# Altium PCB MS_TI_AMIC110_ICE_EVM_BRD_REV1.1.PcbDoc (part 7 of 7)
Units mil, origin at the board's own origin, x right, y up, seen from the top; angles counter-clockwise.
Board outline 3464.57 x 2204.72 mil, 8 copper layers (TopLayer - S1 (.GTL), MidLayer1 - S2 (.G1), MidLayer2 - S3 (.G2), MidLayer3 - S4 (.G3), MidLayer4 - S5 (.G4), MidLayer5 - S6 (.G5), MidLayer6 - S7 (.G6), BottomLayer - S8 (.GBL)), stack 58.937 mil thick; 504 components, 369 nets, 1811 pads, 874 vias.
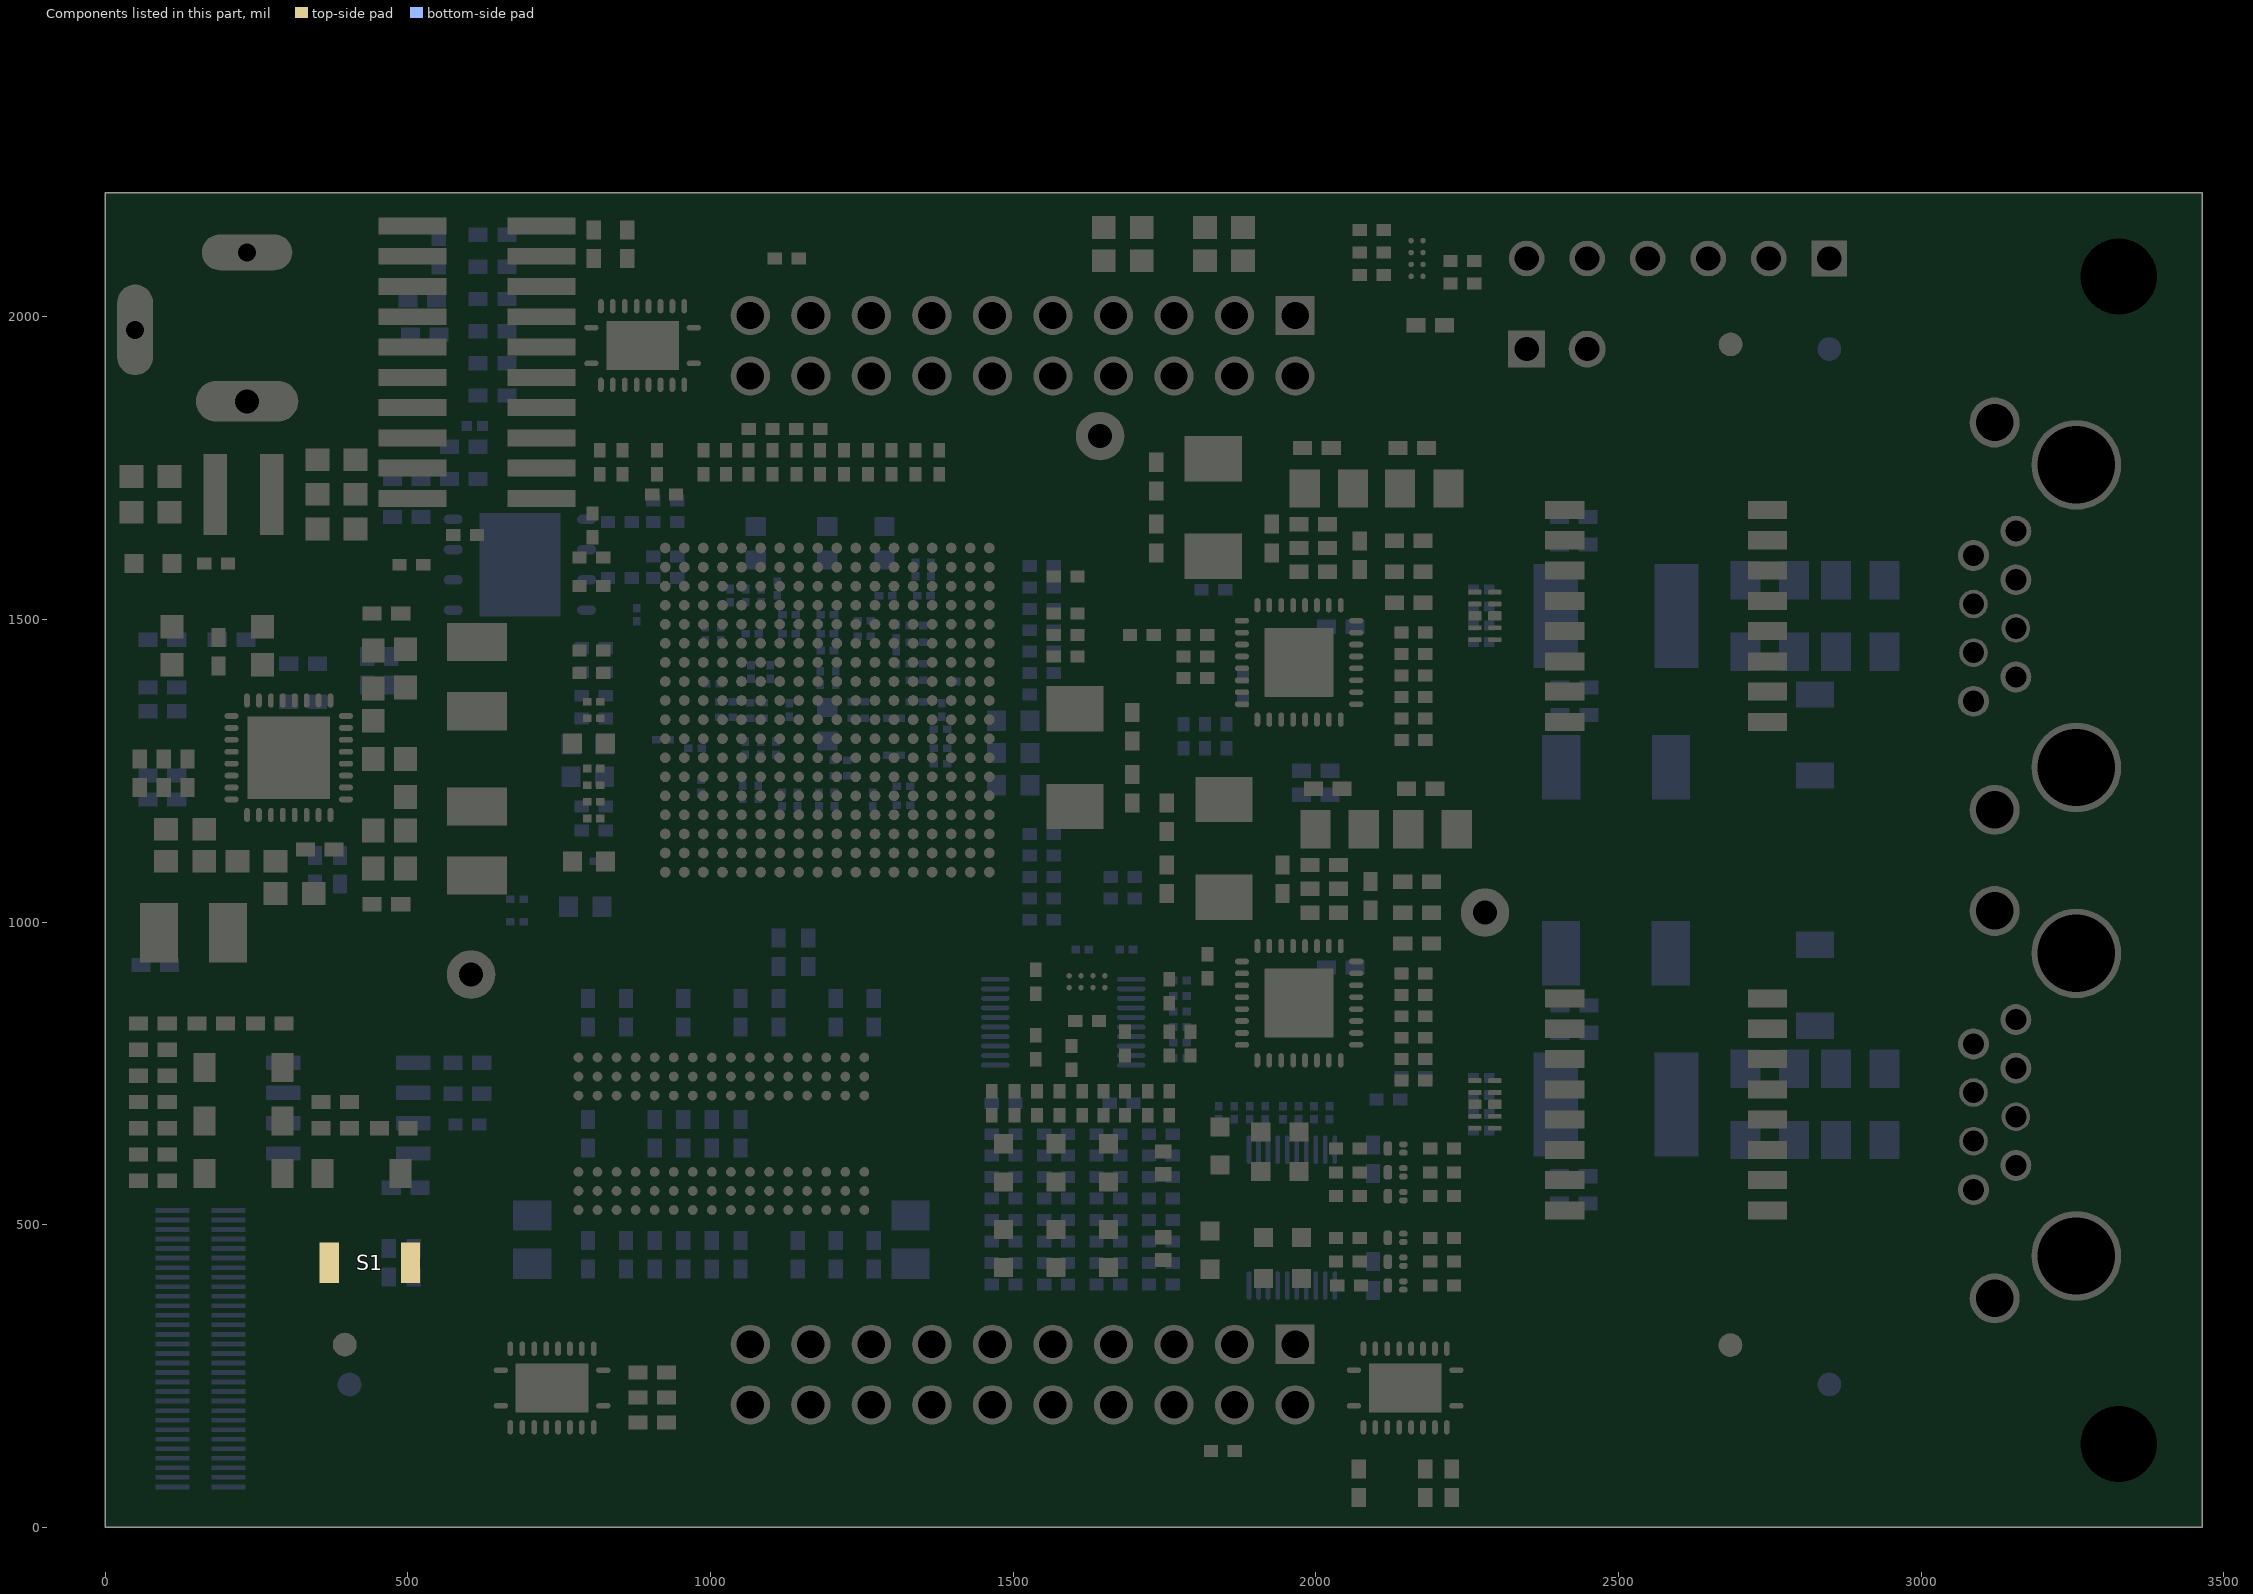
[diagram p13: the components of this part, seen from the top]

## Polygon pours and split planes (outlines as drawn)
GND on BottomLayer - S8 (.GBL) "BOTTOMLAYER_-_S8_(.GBL)_GND_P062" (solid, remove dead copper, pour order 62): 1929.13,1114.17 2409.45,1114.17 2409.45,539.37 2346.46,539.37 2259.84,625.98 2208.66,625.98 2196.85,637.8 2196.85,724.41 2065.94,724.41 2028.54,761.81 1890.75,761.81 1890.75,932.09 1915.35,956.69 1915.35,1100.39
GND on BottomLayer - S8 (.GBL) "BOTTOMLAYER_-_S8_(.GBL)_GND_P052" (solid, remove dead copper, pour order 52): 1965.52,1691.9 2407.48,1691.9 2407.48,1202.76 2297.24,1202.76 2228.35,1271.65 1870.08,1271.65 1870.08,1488.19 1940.94,1559.06 1940.94,1667.32
GND on BottomLayer - S8 (.GBL) "BOTTOMLAYER_-_S8_(.GBL)_GND_P044" (solid, remove dead copper, pour order 44): 501.97,1027.56 511.81,1037.4 511.81,1501.97 501.97,1511.81 33.46,1511.81 23.62,1501.97 23.62,1229.33 145.67,1229.33 145.67,1196.85 222.44,1196.85 237.2,1182.09 237.2,1037.4 247.05,1027.56
ETH1_EARTH on BottomLayer - S8 (.GBL) "Earth1" (solid, remove dead copper, pour order 87): 2549.21,354.33 2964.57,354.33 3003.94,314.96 3385.83,314.96 3425.2,354.33 3425.2,1043.31 3385.83,1082.68 2549.21,1082.68 2509.84,1043.31 2509.84,393.7
ETH2_EARTH on BottomLayer - S8 (.GBL) "Earth2" (solid, remove dead copper, pour order 89): 2549.21,1122.05 3385.83,1122.05 3425.2,1161.42 3425.2,1850.39 3385.83,1889.76 3003.94,1889.76 2964.57,1850.39 2549.21,1850.39 2509.84,1811.02 2509.84,1161.42
GND on BottomLayer - S8 (.GBL) "BOTTOMLAYER_-_S8_(.GBL)_GND_P078" (solid, remove dead copper, pour order 78): 687.99,1497.05 850.39,1497.05 941.93,1497.05 941.93,1527.56 977.36,1527.56 977.36,1624.02 977.36,1693.9 977.36,1710.63 1037.4,1710.63 1068.9,1742.13 1473.43,1742.13 1488.19,1727.36 1488.19,1615.16 1447.83,1615.16 1433.07,1600.39 1433.07,1442.91 1452.76,1423.23 1480.31,1423.23 1488.19,1415.35 1488.19,1383.86 1511.81,1360.24 1578.74,1360.24 1578.74,1167.32 1389.76,1167.32 1383.86,1173.23 1261.81,1173.23 1043.31,1173.23 1011.81,1204.72 996.06,1204.72 992.13,1200.79 992.13,1138.78 917.32,1063.98 878.94,1063.98 863.19,1048.23 863.19,1005.91 851.38,994.09 687.99,994.09
1V1 on MidLayer1 - S2 (.G1) "MIDLAYER1_-_S2_(.G1)_1V1_P099" (solid, remove dead copper, pour order 99): 467.52,1533.46 471.46,1529.53 477.36,1529.53 695.87,1529.53 718.5,1506.89 718.5,1305.12 718.5,1286.42 772.64,1286.42 789.37,1269.68 885.83,1269.68 885.83,1310.04 863.92,1331.94 849.16,1331.94 816.93,1364.17 816.93,1525.59 752.95,1589.57 703.74,1589.57 496.06,1589.57 467.52,1561.02
ETH2_EARTH on MidLayer1 - S2 (.G1) "MidLayer1 - S2 (.G1)-PHY1_EARTH" (solid, remove dead copper, pour order 93): 2763.78,1854.33 3334.65,1854.33 3358.27,1830.71 3358.27,1181.1 3334.65,1157.48 2763.78,1157.48 2740.16,1181.1 2740.16,1830.71
ETH1_EARTH on MidLayer1 - S2 (.G1) "MidLayer1 - S2 (.G1)-PHY1_EARTH" (solid, remove dead copper, pour order 91): 2763.78,1047.24 3334.65,1047.24 3358.27,1023.62 3358.27,374.02 3334.65,350.39 2763.78,350.39 2740.16,374.02 2740.16,1023.62
1V8_2 on MidLayer1 - S2 (.G1) "MIDLAYER1_-_S2_(.G1)_1V8_2_P070" (solid, remove dead copper, pour order 70): 1058.07,1250.98 1058.07,1488.19 1065.94,1488.19 1090.55,1463.58 1220.47,1463.58 1242.13,1441.93 1242.13,1216.54 1027.56,1216.54 1027.56,1240.16 1047.24,1240.16
1V8_1 on MidLayer1 - S2 (.G1) "MIDLAYER1_-_S2_(.G1)_1V8_1_P068" (solid, remove dead copper, pour order 68): 1022.64,1487.2 1022.64,1512.8 1031.5,1521.65 1046.26,1521.65 1077.76,1490.16 1232.28,1490.16 1268.7,1453.74 1268.7,1362.2 1390.75,1362.2 1390.75,1414.37 1369.09,1436.02 1369.09,1589.57 892.72,1589.57 827.76,1524.61 827.76,1368.11 890.75,1305.12 890.75,1267.72 1011.81,1267.72 1027.56,1251.97 1044.29,1251.97 1044.29,1465.55
GND on MidLayer1 - S2 (.G1) "MIDLAYER1_-_S2_(.G1)_GND_P042" (solid, remove dead copper, pour order 42): 1712.6,1792.32 1733.27,1812.99 1930.12,1812.99 1942.91,1800.2 1942.91,1562.99 1982.28,1523.62 1982.28,1471.46 1976.38,1465.55 1922.24,1465.55 1916.34,1471.46 1916.34,1507.87 1867.13,1557.09 1750.98,1557.09 1712.6,1595.47
GND on MidLayer1 - S2 (.G1) "MIDLAYER1_-_S2_(.G1)_GND_P040" (solid, remove dead copper, pour order 40): 1730.31,1250 1932.09,1250 1960.63,1221.46 1960.63,982.28 1982.28,960.63 1982.28,908.46 1976.38,902.56 1922.24,902.56 1916.34,908.46 1916.34,944.88 1867.13,994.09 1770.67,994.09 1730.31,1034.45
GND on MidLayer1 - S2 (.G1) "MIDLAYER1_-_S2_(.G1)_GND_P034" (solid, remove dead copper, pour order 34): 1720.47,1361.22 1720.47,1143.7 1556.1,1143.7 1522.64,1177.17 1522.64,1310.04 1498.03,1334.65 1469.49,1334.65 1419.29,1384.84 1419.29,1411.42 1425.2,1417.32 1527.56,1417.32 1545.28,1399.61 1682.09,1399.61
GND on MidLayer1 - S2 (.G1) "MIDLAYER1_-_S2_(.G1)_GND_P046" (solid, remove dead copper, pour order 46): 27.56,877.95 19.68,885.83 19.68,1511.81 27.56,1519.68 692.91,1519.68 708.66,1503.94 708.66,1043.31 692.91,1027.56 417.32,1027.56 267.72,877.95
GND on MidLayer1 - S2 (.G1) "MIDLAYER1_-_S2_(.G1)_GND_P054" (solid, remove dead copper, pour order 54): 19.68,19.68 19.68,858.27 27.56,866.14 285.43,866.14 435.04,1015.75 606.3,1015.75 696.85,1015.75 718.5,1037.4 718.5,1202.76 718.5,1275.59 768.7,1275.59 785.43,1258.86 967.52,1258.86 1023.62,1202.76 1201.77,1202.76 1201.77,1350.39 1387.8,1350.39 1395.67,1358.27 1395.67,1580.71 1375.98,1600.39 888.78,1600.39 845.47,1557.09 803.15,1557.09 759.84,1600.39 490.16,1600.39 421.26,1531.5 27.56,1531.5 19.68,1539.37 19.68,2185.04 2909.45,2185.04 2909.45,2015.75 2547.24,2015.75 2547.24,1870.08 2476.38,1799.21 2476.38,19.68
3V3 on MidLayer4 - S5 (.G4) "MIDLAYER4_-_S5_(.G4)_3V3_P085" (solid, remove dead copper, pour order 85): 43.31,47.24 43.31,2157.48 2539.37,2157.48 2539.37,1878.94 2464.57,1804.13 2464.57,47.24
1V1 on MidLayer4 - S5 (.G4) "MIDLAYER4_-_S5_(.G4)_1V1_P032" (solid, remove dead copper, pour order 32): 1059.05,1456.69 1088.58,1486.22 1179.13,1486.22 1202.76,1462.6 1246.06,1462.6 1269.64,1486.17 1319.93,1486.17 1327.76,1478.35 1327.76,1412.4 1327.76,1212.6 1064.96,1212.6 1051.18,1198.82 826.77,1198.82 826.77,1309.06 872.05,1354.33 1061.02,1354.33 1082.68,1375.98 1082.68,1413.39 1059.06,1437.01
1V5 on MidLayer4 - S5 (.G4) "MIDLAYER4_-_S5_(.G4)_1V5_P000" (solid, remove dead copper, pour order 0): 1243.11,1201.77 1073.82,1201.77 1059.06,1187.01 826.77,1187.01 637.79,998.03 637.79,905.51 600.39,868.11 600.39,391.73 618.11,374.02 1381.89,374.02 1399.61,391.73 1399.61,1143.7 1361.22,1182.09 1262.8,1182.09 1255.91,1188.98
1V8_1 on MidLayer2 - S3 (.G2) "MIDLAYER2_-_S3_(.G2)_1V8_1_P066" (solid, remove dead copper, pour order 66): 823.82,1362.2 959.65,1362.2 1017.72,1420.28 1017.72,1460.63 1106.3,1549.21 1136.81,1549.21 1159.45,1526.57 1194.88,1526.57 1205.71,1537.4 1205.71,1576.77 1222.44,1593.5 1389.76,1593.5 1389.76,1543.31 1368.11,1521.65 1293.31,1521.65 1135.83,1364.17 1090.55,1364.17 1010.83,1284.45 886.81,1284.45 886.81,1310.24 880.73,1316.93 790.35,1316.93 628.94,1478.35 453.74,1478.35 403.54,1528.54 320.87,1528.54 265.26,1584.15 175.69,1584.15 143.7,1552.17 143.7,1521.65 94.49,1521.65 94.49,1575.79 146.65,1627.95 291.34,1627.95 343.5,1575.79 426.18,1575.79 470.47,1531.5 654.53,1531.5
1V8_2 on MidLayer2 - S3 (.G2) "MIDLAYER2_-_S3_(.G2)_1V8_2_P064" (solid, remove dead copper, pour order 64): 1312.99,1206.69 1358.27,1251.97 1358.27,1510.83 1297.24,1510.83 1140.75,1354.33 1095.47,1354.33 1015.75,1274.61 893.7,1274.61 882.87,1274.61 879.92,1271.65 821.85,1271.65 625,1468.5 548.23,1468.5 548.23,1426.18 767.72,1206.69 893.7,1206.69
VIN5V on MidLayer5 - S6 (.G5) "MIDLAYER5_-_S6_(.G5)_VIN5V_P072" (solid, remove dead copper, pour order 72): 259.84,988.19 39.37,988.19 19.68,1007.87 19.68,1629.92 388.78,1629.92 388.78,1528.54 464.57,1452.76 559.06,1358.27 559.06,1196.85 350.39,988.19 267.72,988.19
GND on MidLayer3 - S4 (.G3) "MIDLAYER3_-_S4_(.G3)_GND_P080" (solid, remove dead copper, pour order 80): 19.68,19.68 2476.38,19.68 2476.38,1799.21 2547.24,1870.08 2547.24,2015.75 2909.45,2015.75 2909.45,2185.04 19.68,2185.04
ETH2_EARTH on MidLayer6 - S7 (.G6) "MidLayer1 - S2 (.G1)-PHY1_EARTH" (solid, remove dead copper, pour order 95): 2763.78,1854.33 3334.65,1854.33 3358.27,1830.71 3358.27,1181.1 3334.65,1157.48 2763.78,1157.48 2740.16,1181.1 2740.16,1830.71
ETH1_EARTH on MidLayer6 - S7 (.G6) "MidLayer1 - S2 (.G1)-PHY1_EARTH" (solid, remove dead copper, pour order 97): 2763.78,1047.24 3334.65,1047.24 3358.27,1023.62 3358.27,374.02 3334.65,350.39 2763.78,350.39 2740.16,374.02 2740.16,1023.62
GND on MidLayer6 - S7 (.G6) "MIDLAYER6_-_S7_(.G6)_GND_P084" (solid, remove dead copper, pour order 84): 19.68,19.68 2476.38,19.68 2476.38,1799.21 2547.24,1870.08 2547.24,2015.75 2909.45,2015.75 2909.45,2185.04 19.68,2185.04

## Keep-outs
Keep-Out Layer:
  text ".Layer_Name" at 25.82,-1252.19 h60

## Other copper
TopLayer - S1 (.GTL):
  region net 3V3: 507.87,1045.28 468.5,1045.28 468.5,970.47 507.87,970.47
  rectangle net 3V3: 2027.56,1203.74 2081.69,1237.2
  rectangle net NetC32_1: 1974.41,1184.06 2011.81,1237.2
  rectangle net NetC36_1: 2127.95,1184.06 2165.35,1237.2
  rectangle net 3V3: 2181.1,1203.74 2235.24,1237.2
  rectangle net 3V3: 2167.32,1766.73 2221.46,1800.2
  rectangle net NetC63_1: 2114.17,1747.05 2151.57,1800.2
  rectangle net NetC55_1: 1956.69,1747.05 1994.09,1800.2
  rectangle net 3V3: 2009.84,1766.73 2063.98,1800.2
  rectangle net 1V1: 468.5,1494.09 507.87,1568.9
  rectangle net NetC177_1: 82.68,1626.97 204.72,1786.42
  region net VIN5V: 374.02,1786.42 251.97,1786.42 251.97,1626.97 374.02,1626.97
  region net VIN5V: 374.02,1661.42 334.65,1661.42 334.65,1586.61 374.02,1586.61
  region net GND: 437.01,1786.42 389.76,1786.42 389.76,1586.61 437.01,1586.61
  rectangle net GND: 389.76,1741.14 437.01,1815.94
  rectangle net GND: 19.68,1654.53 66.93,1804.13
  region net GND: 420.28,1411.42 518.7,1411.42 518.7,1334.65 497.05,1312.99 370.08,1312.99 370.08,1328.74 410.43,1328.74 420.28,1338.58
  region net GND: 420.28,1127.95 518.7,1127.95 518.7,1224.41 516.73,1226.38 414.37,1226.38 410.43,1230.31 370.08,1230.31 370.08,1214.57 408.46,1214.57 420.28,1202.76
  region net 1V1_EN: 420.28,1427.17 694.88,1427.17 694.88,1469.49 666.34,1498.03 562.99,1498.03 539.37,1474.41 465.55,1474.41 460.63,1479.33 460.63,1525.59 420.28,1525.59
  region net 3V3_EN: 420.28,1112.2 694.88,1112.2 694.88,1069.88 666.34,1041.34 562.99,1041.34 539.37,1064.96 466.54,1064.96 460.63,1059.06 460.63,1013.78 420.28,1013.78
  region net NetL1_1: 533.46,1383.86 694.88,1383.86 694.88,1341.54 666.34,1312.99 576.77,1312.99 559.05,1295.28 502.95,1295.28 502.95,1306.1 533.46,1336.61
  region net VIN5V: 386.81,1289.37 382.87,1285.43 382.87,1257.87 386.81,1253.94 420.28,1253.94 424.21,1250 559.06,1250 559.06,1289.37
  region net NetL3_1: 533.46,1155.51 694.88,1155.51 694.88,1197.83 666.34,1226.38 576.77,1226.38 559.05,1244.09 507.87,1244.09 533.46,1218.5
  region net VIN5V: 297.24,1191.93 301.18,1187.99 301.18,1006.89 294.29,1000 261.81,1000 261.81,1120.08 285.43,1143.7 285.43,1187.99 289.37,1191.93
  region net NetC72_2: 307.09,1144.68 307.09,1028.54 346.46,1028.54 346.46,1134.84 343.5,1137.8 325.79,1137.8 318.9,1144.68
  region net GND: 344.49,1206.69 344.49,1166.34 348.43,1162.4 348.43,1143.7 352.36,1139.76 352.36,1104.33 397.64,1104.33 397.64,1135.83 395.67,1137.8 375.98,1137.8 361.22,1152.56 361.22,1206.69
  region net GND: 139.76,1176.18 139.76,1077.76 236.22,1077.76 238.19,1079.72 238.19,1129.92 261.81,1153.54 261.81,1226.38 246.06,1226.38 246.06,1166.34 239.17,1159.45 216.54,1159.45 199.8,1176.18
  region net NetL2_1: 167.32,1062.99 167.32,901.57 209.65,901.57 238.19,930.12 238.19,1031.5 255.91,1049.21 255.9,1088.58 230.31,1062.99
  region net NetC74_1: 124.02,1176.18 124.02,901.57 81.69,901.57 53.15,930.12 53.15,1033.46 76.77,1057.09 76.77,1126.97 70.87,1132.87 37.4,1132.87 37.4,1176.18
  region net GND: 285.43,1336.61 285.43,1449.8 280.51,1454.72 87.6,1454.72 87.6,1511.81 295.28,1511.81 302.17,1504.92 302.17,1336.61
  region net NetC87_1: 216.54,1444.88 220.47,1448.82 276.57,1448.82 279.53,1445.87 279.53,1387.8 268.7,1387.8 254.92,1401.57 220.47,1401.57 216.54,1405.51
  region net VIN5V: 151.57,1444.88 155.51,1448.82 198.82,1448.82 202.76,1444.88 202.76,1410.43 218.5,1394.68 218.5,1383.86 205.71,1383.86 179.13,1383.86 151.57,1411.42
  region net 1V8_1_EN: 65.94,1444.88 69.88,1448.82 128.94,1448.82 132.87,1444.88 132.87,1421.26 176.18,1377.95 234.25,1377.95 234.25,1357.28 161.42,1357.28 117.13,1401.57 69.88,1401.57 65.94,1405.51
  region net SPI0_SCLK: 614.17,1623.03 620.99,1613.68 607.91,1613.68
  text "S1" at 2598.43,1868.11 h35.43 r90
  text ".Layer_Name" at 25.82,-1252.19 h60
MidLayer1 - S2 (.G1):
  text "S2" at 2647.05,1865.29 h35.43 r90
  text ".Layer_Name" at 24.82,-1252.69 h60
MidLayer2 - S3 (.G2):
  rectangle net 1V8_1: 1368.11,1368.11 1422.24,1431.1
  pour cut-out: 1740.16,1122.05 cw(c1753.94,1122.05) 1753.94,1135.83 cw(c1753.94,1122.05) 1767.72,1122.05 cw(c1753.94,1122.05) 1753.94,1108.27 cw(c1753.94,1122.05)
  pour cut-out: 1696.85,1285.43 cw(c1696.85,1271.65) 1710.63,1271.65 cw(c1696.85,1271.65) 1696.85,1257.87 cw(c1696.85,1271.65) 1683.07,1271.65 cw(c1696.85,1271.65)
  pour cut-out: 1722.44,1685.04 cw(c1736.22,1685.04) 1736.22,1698.82 cw(c1736.22,1685.04) 1750,1685.04 cw(c1736.22,1685.04) 1736.22,1671.26 cw(c1736.22,1685.04)
  text "S3" at 2696.85,1868.11 h35.43 r90
  text ".Layer_Name" at 24.82,-1252.69 h60
MidLayer3 - S4 (.G3):
  pour cut-out: 151.57,1517.71 cw(c151.58,1501.97) 167.32,1501.97 cw(c151.58,1501.97) 151.57,1486.22 cw(c151.58,1501.97) 135.83,1501.97 cw(c151.57,1501.97)
  pour cut-out: 226.38,1517.71 cw(c226.38,1501.97) 242.13,1501.97 cw(c226.38,1501.97) 226.38,1486.22 cw(c226.38,1501.97) 210.63,1501.97 cw(c226.38,1501.97)
  pour cut-out: 1740.16,1122.05 cw(c1753.94,1122.05) 1753.94,1135.83 cw(c1753.94,1122.05) 1767.72,1122.05 cw(c1753.94,1122.05) 1753.94,1108.27 cw(c1753.94,1122.05)
  pour cut-out: 1696.85,1285.43 cw(c1696.85,1271.65) 1710.63,1271.65 cw(c1696.85,1271.65) 1696.85,1257.87 cw(c1696.85,1271.65) 1683.07,1271.65 cw(c1696.85,1271.65)
  pour cut-out: 1722.44,1685.04 cw(c1736.22,1685.04) 1736.22,1698.82 cw(c1736.22,1685.04) 1750,1685.04 cw(c1736.22,1685.04) 1736.22,1671.26 cw(c1736.22,1685.04)
  text "S4" at 2746.06,1868.11 h35.43 r90
  text ".Layer_Name" at 24.82,-1252.69 h60
MidLayer4 - S5 (.G4):
  pour cut-out: 1740.16,1122.05 cw(c1753.94,1122.05) 1753.94,1135.83 cw(c1753.94,1122.05) 1767.72,1122.05 cw(c1753.94,1122.05) 1753.94,1108.27 cw(c1753.94,1122.05)
  pour cut-out: 1696.85,1285.43 cw(c1696.85,1271.65) 1710.63,1271.65 cw(c1696.85,1271.65) 1696.85,1257.87 cw(c1696.85,1271.65) 1683.07,1271.65 cw(c1696.85,1271.65)
  pour cut-out: 1722.44,1685.04 cw(c1736.22,1685.04) 1736.22,1698.82 cw(c1736.22,1685.04) 1750,1685.04 cw(c1736.22,1685.04) 1736.22,1671.26 cw(c1736.22,1685.04)
  text "S5" at 2746.06,2001.97 h35.43 r90
  text ".Layer_Name" at 24.82,-1252.69 h60
MidLayer5 - S6 (.G5):
  text "S6" at 2696.85,2001.97 h35.43 r90
  text ".Layer_Name" at 24.82,-1252.69 h60
MidLayer6 - S7 (.G6):
  pour cut-out: 151.57,1517.71 cw(c151.58,1501.97) 167.32,1501.97 cw(c151.58,1501.97) 151.57,1486.22 cw(c151.58,1501.97) 135.83,1501.97 cw(c151.57,1501.97)
  pour cut-out: 226.38,1517.71 cw(c226.38,1501.97) 242.13,1501.97 cw(c226.38,1501.97) 226.38,1486.22 cw(c226.38,1501.97) 210.63,1501.97 cw(c226.38,1501.97)
  pour cut-out: 1696.85,1285.43 cw(c1696.85,1271.65) 1710.63,1271.65 cw(c1696.85,1271.65) 1696.85,1257.87 cw(c1696.85,1271.65) 1683.07,1271.65 cw(c1696.85,1271.65)
  pour cut-out: 1722.44,1685.04 cw(c1736.22,1685.04) 1736.22,1698.82 cw(c1736.22,1685.04) 1750,1685.04 cw(c1736.22,1685.04) 1736.22,1671.26 cw(c1736.22,1685.04)
  pour cut-out: 1740.16,1122.05 cw(c1753.94,1122.05) 1753.94,1135.83 cw(c1753.94,1122.05) 1767.72,1122.05 cw(c1753.94,1122.05) 1753.94,1108.27 cw(c1753.94,1122.05)
  text "S7" at 2647.64,2001.97 h35.43 r90
  text ".Layer_Name" at 24.82,-1252.69 h60
BottomLayer - S8 (.GBL):
  rectangle net NetC184_1: 2760.83,604.33 2888.78,854.33
  rectangle net 1V5: 87.6,905.51 116.14,950.79
  rectangle net NetC74_1: 23.62,905.51 78.74,1177.17
  rectangle net 1V8_1_EN: 55.12,1406.5 86.61,1478.35
  rectangle net NetC87_1: 216.54,1406.5 248.03,1478.35
  region net 1V8_1: 135.83,1567.91 100.39,1567.91 100.39,1452.76 135.83,1452.76
  region net 1V8_2: 202.76,1567.91 167.32,1567.91 167.32,1452.76 202.76,1452.76
  region net NetC186_1: 2888.78,1600.39 2760.83,1600.39 2760.83,1350.39 2888.78,1350.39
  pour cut-out: 2641.73,553.15 2704.72,490.16 3145.67,490.16 3225.65,570.14 3225.66,862.93 3179.33,909.25 2706.5,909.25 2641.73,844.49
  pour cut-out: 2641.73,1360.24 2704.73,1297.24 3145.67,1297.24 3225.65,1377.23 3225.66,1670.01 3179.33,1716.34 2705.51,1716.34 2641.73,1652.56
  pour cut-out: 1740.16,1122.05 cw(c1753.94,1122.05) 1753.94,1135.83 cw(c1753.94,1122.05) 1767.72,1122.05 cw(c1753.94,1122.05) 1753.94,1108.27 cw(c1753.94,1122.05)
  pour cut-out: 1696.85,1285.43 cw(c1696.85,1271.65) 1710.63,1271.65 cw(c1696.85,1271.65) 1696.85,1257.87 cw(c1696.85,1271.65) 1683.07,1271.65 cw(c1696.85,1271.65)
  pour cut-out: 1722.44,1685.04 cw(c1736.22,1685.04) 1736.22,1698.82 cw(c1736.22,1685.04) 1750,1685.04 cw(c1736.22,1685.04) 1736.22,1671.26 cw(c1736.22,1685.04)
  text "S8" at 2598.43,2001.97 h35.43 r90
  text ".Layer_Name" at 25.82,-1252.19 h60

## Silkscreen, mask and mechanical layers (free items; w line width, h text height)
Top Overlay:
  circle w7.87: c423.22,1202.95 r3.94
  lines w0.5: 1257.7,789.42 cw(c1267.92,800.4) 1252.92,800.4 cw(c1267.92,800.4) 1267.92,815.4 cw(c1267.92,800.4) 1282.92,800.4 cw(c1267.92,800.4) 1267.92,785.4 cw(c1267.92,800.4) 1263.62,786.03
  lines w3.94: 10.13,617.97 15.75,616.14 ; 10.13,791.19 15.75,789.37 ; 12.28,611.36 15.75,616.14 ; 12.28,784.59 15.75,789.37 ; 15.75,622.05 15.75,616.14 ; 15.75,639.76 15.75,649.61 ; 15.75,659.45 15.75,669.29 ; 15.75,679.13 15.75,688.98 ; 15.75,698.82 15.75,708.66 ; 15.75,718.5 15.75,728.35 ; 15.75,738.19 15.75,748.03 ; 15.75,757.87 15.75,767.72 ; 15.75,795.28 15.75,789.37 ; 19.22,611.36 15.75,616.14 ; 19.22,784.59 15.75,789.37 ; 21.36,617.97 15.75,616.14 ; 21.36,791.2 15.75,789.37 ; 115.16,1648.62 115.16,1633.86 136.81,1612.2 223.43,1612.2 ; 207.68,1575.79 226.38,1557.09 ; 216.54,1611.22 222.44,1605.32 222.44,1591.54 228.35,1585.63 ; 333.66,804.13 333.66,865.16 342.52,874.02 359.25,874.02 ; 333.66,812.99 359.25,812.99 ; 333.66,843.5 339.57,843.5 359.25,843.5 ; 380.91,1585.63 380.91,1622.05 ; 437.01,688.98 460.63,702.76 ; 469.49,1316.93 532.48,1316.93 538.39,1311.02 ; 520.67,1237.2 567.91,1237.2 ; 522.64,1060.04 545.28,1037.4 ; 523.62,1479.33 542.32,1498.03 542.32,1517.72 ; 597.73,614.32 603.35,616.14 ; 597.73,728.2 603.35,726.38 ; 599.88,620.92 603.35,616.14 ; 599.88,721.6 603.35,726.38 ; 603.35,610.24 603.35,616.14 ; 603.35,633.86 603.35,643.7 ; 603.35,655.51 603.35,665.35 ; 603.35,677.17 603.35,687.01 ; 603.35,698.82 603.35,708.66 ; 603.35,732.28 603.35,726.38 ; 606.82,620.92 603.35,616.14 ; 606.82,721.6 603.35,726.38 ; 608.96,614.32 603.35,616.14 ; 608.96,728.2 603.35,726.38 ; 713.58,1321.85 755.91,1364.17 780.51,1364.17 ; 730.32,1305.12 761.81,1336.61 780.51,1336.61 ; 732.28,1047.24 732.28,1215.55 770.67,1253.94 780.51,1253.94 ; 732.28,1138.78 744.34,1150.84 764.76,1171.26 780.51,1171.26 ; 732.28,1163.39 744.34,1175.44 767.72,1198.82 780.51,1198.82 ; 732.28,1192.91 744.34,1204.97 ; 741.14,1461.61 741.14,1433.07 762.8,1411.42 ; 780.51,1226.38 765.75,1226.38 744.34,1204.97 ; 784.45,1673.23 787.4,1676.18 787.4,1703.74 806.1,1722.44 ; 819.88,1467.52 819.88,1490.16 ; 827.76,2071.85 842.52,2057.09 890.75,2057.09 ; 1047.24,1669.29 1080.71,1669.29 1102.36,1690.94 1102.36,1718.5 ; 1047.24,1700.79 1057.09,1700.79 1062.99,1706.69 1062.99,1718.5 ; 1141.73,1718.5 1141.73,1690.94 1163.39,1669.29 1196.85,1669.29 ; 1181.1,1718.5 1181.1,1706.69 1187.01,1700.79 1196.85,1700.79 ; 1535.43,1585.63 1535.43,1452.76 1547.24,1440.94 ; 1666.34,1499.02 1676.18,1489.17 ; 1720.47,1412.4 1752.95,1412.4 1764.76,1424.21 ; 1739.17,1442.91 1748.03,1442.91 1764.76,1459.65 ; 1763.78,1559.06 1929.13,1559.06 1937.99,1567.91 ; 1796.26,1548.23 1838.58,1548.23 ; 1832.68,1520.67 1832.68,1530.51 1836.61,1534.45 ; 1841.54,1539.37 1845.47,1543.31 1851.38,1543.31 ; 1859.25,1548.23 1965.55,1548.23 2055.12,1548.23 2058.07,1551.18 2058.07,1556.1 ; 2062.01,1102.36 2279.53,1102.36 2350.39,1102.36 ; 2091.54,423.23 2096.46,418.31 2096.46,389.76 ; 2091.54,462.6 2104.33,449.8 2104.33,389.76 ; 2091.54,562.99 2104.33,575.79 2104.33,635.83 ; 2091.54,602.36 2096.46,607.28 2096.46,635.83 ; 2111.22,1091.54 2122.05,1102.36 ; 2149.61,642.72 2149.61,660.43 ; 2155.51,454.72 2158.46,457.68 2158.46,485.24 ; 2155.51,602.36 2158.46,605.31 2158.46,658.46 2162.4,662.4 ; 2156.5,416.34 2166.34,426.18 2166.34,490.16 2169.29,493.11 ; 2156.5,563.98 2166.34,573.82 2166.34,648.62 2173.23,655.51 2185.04,655.51 2191.93,662.4 ; 2213.58,811.02 2213.58,818.9 ; 2213.58,829.72 2213.58,837.6 ; 2213.58,1373.03 2213.58,1380.91 ; 2213.58,1391.73 2213.58,1399.61 ; 2214.57,1087.6 2387.8,1087.6 ; 2222.44,1564.96 2222.44,1572.83 ; 2222.44,1583.66 2222.44,1591.54 ; 2277.56,1102.36 2284.45,1109.25 ; 744.34,1204.97 744.34,1204.97
  text "LaunchPad" at 2061.02,2047.24 h43.31 r270
  text "3V3" at 2015.75,2033.46 h43.31 r270
  text "5V0" at 2015.75,1934.06 h43.31 r270
  text "Assy PN:4P0063" at 861.9,434.31 h21.65
  text "REV:1.1" at 2518.76,376.63 h32
  text "RESET" at 381.08,350.14 h43.31
  text ".Layer_Name" at 25.82,-1252.19 h60
Bottom Overlay:
  drawing of 236 lines, arcs and shapes, not listed
  text ".Layer_Name" at 25.82,-1252.19 h60
Top Paste:
  text ".Layer_Name" at 25.82,-1252.19 h60
Bottom Paste:
  lines w0.5: 836.11,430.4 ccw(c848.61,430.4) 848.61,417.9 ccw(c848.61,430.4) 861.11,430.4 ccw(c848.61,430.4) 848.61,442.9 ccw(c848.61,430.4) 836.11,430.4 ; 836.11,470.4 ccw(c848.61,470.4) 848.61,457.9 ccw(c848.61,470.4) 861.11,470.4 ccw(c848.61,470.4) 848.61,482.9 ccw(c848.61,470.4) 836.11,470.4
  text ".Layer_Name" at 25.82,-1252.19 h60
Top Solder:
  text ".Layer_Name" at 25.82,-1252.19 h60
  text ".Layer_Name" at 25.82,-1252.19 h60
Bottom Solder:
  text ".Layer_Name" at 25.82,-1252.19 h60
Drill Guide:
  text ".Layer_Name" at 25.82,-1252.19 h60
M1 Board Outline:
  the board outline again, w10
M2 Board Dimensions:
  rectangle: 236.22,-275 361.22,-150
  rectangle: 361.22,-400 736.22,-275
  lines w7: 236.22,-275 1236.22,-275 ; 361.22,-400 361.22,-150 ; 486.22,-400 486.22,-150 ; 736.22,-400 736.22,-150 ; 986.22,-400 986.22,-150 ; 236.22,-400 1236.22,-400 1236.22,-150 236.22,-150 236.22,-400
  text ".Layer_Name" at 25.82,-1252.19 h60
M3 3D STEP Top:
  text ".Layer_Name" at 25.82,-1252.19 h60
M4 3D STEP Bottom:
  text ".Layer_Name" at 25.82,-1252.19 h60
M5 Assembly Top:
  lines w10: -843.18,-1323.87 5756.82,-1323.87 ; -843.18,-1120.53 5758.82,-1120.53 ; -843.18,-917.2 -843.18,-1527.2 3161.82,-1527.2 5758.82,-1527.2 5758.82,-917.2 -842.68,-917.2 -842.68,-1527.2 732.82,-1527.2 ; 1621.82,-1527.2 1621.82,-917.2 ; 2888.82,-1120.53 2888.82,-917.2 ; 3728.82,-1120.53 3728.82,-917.2 ; 4350.82,-1533.7 4350.82,-1330.87
  text "COMPONENTS MARKED 'DNP' SHOULD NOT BE POPULATED." at 1389.72,-318.5 h60
  text "ASSEMBLY VARIANT:" at 1389.22,-434 h60
  text ".VariantName" at 2425.22,-434 h60
  text "PCB VIEWED FROM TOP SIDE" at -779.68,-1049.37 h60
  text "BOARD #:" at 1696.82,-1049.37 h60
  text ".PRJ_Number" at 2242.32,-1049.37 h60
  text "REV:" at 3086.82,-1049.37 h60
  text ".PCB_Rev" at 3378.32,-1049.37 h60
  text "SVN REV:" at 3924.82,-1049.37 h60
  text ".VersionControl_RevNumber" at 4430.82,-1049.37 h60
  text "TID #:" at 1696.82,-1252.7 h60
  text ".TID" at 2242.32,-1252.7 h60
  text "PLOT NAME =" at -779.68,-1458.04 h60
  text ".plot_File_Name" at 25.82,-1458.04 h60
  text "GENERATED    :" at 1698.82,-1458.04 h60
  text ".Print_Date" at 2568.32,-1458.04 h60
  text ".Print_Time" at 3297.32,-1458.04 h60
  text "TEXAS INSTRUMENTS" at 4561.82,-1458.04 h60
M6 Assembly Bottom:
  lines w10: -843.68,-1121.03 5758.32,-1121.03 ; -841.68,-1324.37 5758.32,-1324.37 ; 564.32,-1534.2 564.32,-1331.37 ; 1186.32,-1121.03 1186.32,-917.7 ; 2026.32,-1121.03 2026.32,-917.7 ; 3293.32,-1527.7 3293.32,-917.7 ; 4182.32,-1527.7 5757.82,-1527.7 5757.82,-917.7 -843.68,-917.7 -843.68,-1527.7 1753.32,-1527.7 5758.32,-1527.7 5758.32,-917.7
  text "COMPONENTS MARKED 'DNP' SHOULD NOT BE POPULATED." at 5550.82,-711.7 h60
  text ".VariantName" at 4506.82,-827.7 h60
  text "ASSEMBLY VARIANT:" at 5545.82,-827.7 h60
  text ".VersionControl_RevNumber" at 484.32,-1049.87 h60
  text "SVN REV:" at 990.32,-1049.87 h60
  text ".PCB_Rev" at 1536.82,-1049.87 h60
  text "REV:" at 1828.32,-1049.87 h60
  text ".PRJ_Number" at 2672.82,-1049.87 h60
  text "BOARD #:" at 3218.32,-1049.87 h60
  text "PCB VIEWED FROM BOTTOM SIDE" at 5694.82,-1049.87 h60
  text ".TID" at 2672.82,-1253.2 h60
  text "TID #:" at 3218.32,-1253.2 h60
  text "TEXAS INSTRUMENTS" at 353.32,-1458.54 h60
  text ".Print_Time" at 1617.82,-1458.54 h60
  text ".Print_Date" at 2346.82,-1458.54 h60
  text "GENERATED    :" at 3216.32,-1458.54 h60
  text ".plot_File_Name" at 4889.32,-1458.54 h60
  text "PLOT NAME =" at 5694.82,-1458.54 h60
M9 Title Sheet:
  drawing of 57 lines, arcs and shapes, not listed
  text "1" at 188.66,7642.8 h70
  text "2" at 2684.32,7642.8 h70
  text "3" at 5173.66,7642.8 h70
  text "4" at 7680.33,7642.8 h70
  text "5" at 10179.32,7642.8 h70
  text "6" at 12684.32,7642.8 h70
  text "A" at -967.68,6499.8 h70
  text "A" at 13832.32,6499.8 h70
  text "B" at -967.68,4119.8 h70
  text "B" at 13832.32,4119.8 h70
  text "C" at -967.68,1744.8 h70
  text "C" at 13832.32,1744.8 h70
  text "PROJECT TITLE:" at 10792.32,-116.2 h45
  text "AMIC110  ICE EVM" at 10842.32,-249.53 h70
  text "DESIGNED FOR:" at 10792.32,-417.2 h45
  text "TEXAS INSTRUMENTS" at 10842.32,-557.2 h70
  text "D" at -967.68,-625.2 h70
  text "D" at 13832.32,-625.2 h70
  text "FILE NAME:" at 10792.32,-717.2 h45
  text ".PCB_File_Name_No_Path" at 10842.32,-837.2 h70
  text "Texas Instruments (TI) and/or its licensors do not warrant the accuracy or completeness of this specification" at 5822.82,-999.04 h45
  text "ENGINEER:" at 10792.32,-1007.2 h45
  text "LAYOUT BY:" at 12297.32,-1007.2 h45
  text "or any information contained therein. TI and/or its licensors do not warrant that this design will meet" at 5777.83,-1111.7 h45
  text ".PRJ_Engineer" at 10842.32,-1162.19 h70
  text ".PCB_Layout" at 12347.82,-1162.19 h70
  text "the specifications, will be suitable for your application or fit for any particular purpose, or will operate in" at 5777.83,-1224.37 h45
  text ".Layer_Name" at 25.82,-1252.19 h60
  text "ALTIUM DESIGNER VERSION:" at 12297.32,-1317.2 h45
  text "an implementation. TI and/or its licensors do not warrant that the design is production worthy. You should" at 5777.83,-1337.04 h45
  text "completely validate and test your design implementation to confirm the system functionality for your application." at 5822.82,-1449.7 h45
  text ".print_Scale" at 10842.32,-1450.53 h70
  text ".Application_BuildNumber" at 12347.82,-1450.53 h70
  text "1" at 188.66,-1657.2 h70
  text "2" at 2684.32,-1657.2 h70
  text "3" at 5173.66,-1657.2 h70
  text "4" at 7680.33,-1657.2 h70
  text "5" at 10179.32,-1657.2 h70
  text "6" at 12684.32,-1657.2 h70
M10 Fab Notes:
  drawing of 173 lines, arcs and shapes, not listed
  text "DESIGN INFORMATION" at 11826.84,6107.3 h60
  text "3.967" at 12045.9,5932.96 h60
  text "MIN. TRACK WIDTH:" at 11182.28,5927.3 h60
  text "MIL" at 12433.28,5927.3 h60
  text "3.937" at 12069.37,5799.33 h60
  text "MIN. CLEARANCE:" at 11182.28,5795.3 h60
  text "MIL" at 12433.28,5795.3 h60
  text "17.716" at 12093.05,5665.32 h60
  text "MIN. VIA PAD SIZE:" at 11182.28,5663.3 h60
  text "MIL" at 12433.28,5663.3 h60
  text "0.05mm (2MIL)" at 11877.28,5521.59 h60
  text "MINIMUM ANNULAR RING" at 10853.05,5517.3 h60
  text "EXTERNAL" at 12585.28,5517.3 h60
  text "PER" at 11053.05,5399.3 h60
  text "IPC-D-275 CLASS 2 LEVEL C" at 11273.05,5399.3 h60
  text "MIL, HOLES" at 12761.28,5287.01 h60
  text "+/-" at 12368.82,5286.3 h60
  text "+/-" at 13222.82,5286.3 h60
  text "REGISTRATION TOLERANCES:" at 10853.05,5281.3 h60
  text "PTH" at 12102.82,5281.3 h60
  text "2" at 12629.02,5281.3 h60
  text "3" at 13462.02,5281.3 h60
  text "MIL" at 13578.28,5281.3 h60
  text "+/-" at 13222.82,5168.3 h60
  text "HOLE SIZE TOLERANCE (UNLESS OTHERWISE SPECIFIED):" at 10853.05,5163.3 h60
  text "3" at 13462.02,5163.3 h60
  text "MIL" at 13578.28,5163.3 h60
  text "MATERIAL:" at 10778.28,4953.84 h60
  text "FR-4 High Tg" at 11764.72,4813.51 h60
  text "FR-408" at 11199.28,4804.94 h60
  text "OTHER" at 12687.28,4804.94 h60
  text "X" at 11609.82,4801.3 h60
  text "62 MIL (1.6mm) +/-10%" at 11519.38,4642.22 h60
  text "THICKNESS:" at 10853.05,4637.94 h60
  text "X" at 11391.22,4637.94 h60
  text "OTHER" at 12804.28,4637.94 h60
  text "TOLERANCE:" at 10853.05,4479.94 h60
  text "X" at 11692.35,4479.94 h60
  text "ANSI IPC-6012 TYPE 3 CLASS 2" at 11879.29,4479.94 h60
  text "OTHER +/-" at 11879.28,4323.94 h60
  text "BOW & TWIST:" at 10853.05,4166.94 h60
  text "X" at 11692.35,4166.94 h60
  text "ANSI IPC-6012 TYPE 3 CLASS 2" at 11879.29,4166.94 h60
  text "OTHER +/-" at 11879.28,4008.43 h60
  text "DRILLING:" at 10778.28,3869.94 h60
  text "REFERENCE:" at 10853.05,3752.94 h60
  text "X" at 11501.28,3752.94 h60
  text "AS SHOWN" at 11688.28,3752.94 h60
  text "X" at 12402.28,3752.94 h60
  text "NC_DRILL FILES" at 12539.28,3752.94 h60
  text "IPC-6012" at 13222.45,3665.71 h60
  text "PTH MIN COPPER THICKNESS:" at 10853.05,3594.94 h60
  text "1MIL" at 12340.28,3594.94 h60
  text "X" at 12735.98,3594.94 h60
  text "OTHER" at 12837.28,3594.94 h60
  text "CLASS 2" at 13218.94,3574.45 h60
  text "BOARD FINISH:" at 10778.28,3435.94 h60
  text "SILKSCREEN:" at 10933.5,3317.94 h60
  text "X" at 11882.28,3317.94 h60
  text "TOP" at 12008.28,3317.94 h60
  text "X" at 12392.28,3317.94 h60
  text "BOTTOM" at 12519.28,3317.94 h60
  text "SILKSCREEN COLOR:" at 10933.5,3150.94 h60
  text "X" at 11881.24,3150.94 h60
  text "WHITE" at 12008.28,3150.94 h60
  text "OTHER" at 12519.28,3150.94 h60
  text "BLUE" at 13190.85,2995.26 h60
  text "GREEN" at 12139.28,2991.74 h60
  text "X" at 12608.98,2991.74 h60
  text "OTHER" at 12757.28,2991.74 h60
  text "SOLDER RESIST COLOR:" at 10933.5,2980.94 h60
  text "X" at 12012.24,2821.74 h60
  text "MATTE" at 12139.28,2821.74 h60
  text "SEMI-GLOSS" at 12756.82,2821.1 h60
  text "IMMERSION GOLD (ENIG)" at 11839.28,2633.22 h60
  text "ENEPIG" at 13176.82,2629.94 h60
  text "SURFACE FINISH:" at 10778.28,2628.94 h60
  text "X" at 11652.33,2628.94 h60
  text "IMM. TIN/SILVER OR EQUIV" at 11107.82,2471.94 h60
  text "OTHER" at 12539.28,2471.94 h60
  text "ARRAY/PANEL:" at 10778.28,2292.94 h60
  text "CUT AND TRIM PER M1 BOARD OUTLINE" at 11839.28,2288.65 h60
  text "N.C. ROUTE" at 11839.28,2136.94 h60
  text "X" at 12518.28,2136.94 h60
  text "V. SCORE" at 12705.28,2136.94 h60
  text "TEAR DROPS SHALL BE ADDED FOR ALL THE VIAS IN BOTH THE" at 10775.34,1983.66 h60
  text "INTERNAL AND EXTERNAL LAYERS." at 10775.34,1847.19 h60
  text "CERTIFICATION:" at 10778.28,1699.94 h60
  text "MATERIALS AND WORKMANSHIP FOR ALL PCBS" at 11503.28,1699.94 h60
  text "TO MEET OR EXCEED THE REQUIREMENTS OF:" at 11503.28,1601.94 h60
  text "X" at 11129.78,1465.43 h60
  text "ANSI IPC-A-600F CLASS ->" at 11268.78,1465.43 h60
  text "X" at 12907.84,1465.43 h60
  text "2" at 13026.78,1465.43 h60
  text "1" at 12711.78,1463.94 h60
  text "3" at 13380.78,1463.94 h60
  text "X" at 11943.84,1305.94 h60
  text "RoHS" at 12080.78,1305.94 h60
  text "OTHER" at 12725.18,1305.94 h60
  text "PER ORDER" at 13122.24,1305.94 h60
  text "ALL BOARDS MUST MEET OR EXCEED UL94-V0 REQUIREMENTS." at 10805.82,1140.3 h60
  text "PCB MUST BEAR THE UL94V-0 UL REGISTERED MATERIAL ID NUMBER" at 10805.82,1020.3 h60
  text "ADDITIONAL REQUIREMENTS:" at 10778.28,846.94 h60
  text "MICROSECTION:" at 10853.05,731.94 h60
  text "YES" at 11758.78,731.94 h60
  text "REQUIRED" at 12620.28,575.79 h60
  text "BARE BOARD ELEC. TEST:" at 10853.05,572.94 h60
  text "NONE" at 12158.78,572.94 h60
  text "X" at 12493.28,572.94 h60
  text "PER ORDER" at 13212.28,572.94 h60
  text ".Layer_Name" at 25.82,-1252.19 h60
M11 Gerber Information:
  lines w10: -843.18,-1323.87 5756.82,-1323.87 ; -843.18,-1120.53 5758.82,-1120.53 ; -843.18,-917.2 -843.18,-1527.2 3161.82,-1527.2 5758.82,-1527.2 5758.82,-917.2 -842.68,-917.2 -842.68,-1527.2 732.82,-1527.2 ; 1621.82,-1321.34 1621.82,-917.2 ; 2552.44,-1526.66 2552.44,-1323.82 ; 3088.82,-1120.53 3088.82,-917.2 ; 3728.82,-1120.53 3728.82,-917.2 ; 4728.81,-1531.66 4728.81,-1328.83
  text "ALL ARTWORK VIEWED FROM TOP SIDE" at -779.68,-1049.37 h60
  text "BOARD #:" at 1696.82,-1049.37 h60
  text "TMDXICE110" at 2242.32,-1049.37 h60
  text "REV:" at 3186.82,-1049.37 h60
  text "1.1" at 3478.32,-1049.37 h60
  text "SVN REV:" at 3924.82,-1049.37 h60
  text ".VersionControl_RevNumber" at 4430.82,-1049.37 h60
  text "LAYER NAME =" at -779.68,-1252.19 h60
  text "TID #:" at 1696.82,-1252.7 h60
  text "NA" at 2242.32,-1252.7 h60
  text "GENERATED    :" at 2581,-1449.59 h60
  text ".Print_Date" at 3450.5,-1449.59 h60
  text ".Print_Time" at 4179.5,-1449.59 h60
  text "TEXAS INSTRUMENTS" at 4740.78,-1450.13 h60
  text ".plot_File_Name" at -65.9,-1451.18 h60
  text "PLOT NAME =" at -779.68,-1458.04 h60
M12 Stackup:
  drawing of 1610 lines, arcs and shapes, not listed
  text "LAYER STACKUP" at 1203.62,6834.28 h100
  text "LAYER STACKUP" at 1203.62,6834.28 h100
  text "LAYER NAME" at 1986.12,6509.28 h100
  text "LAYER NAME" at 1986.12,6509.28 h100
  text "FINISHED Cu" at 3858.62,6509.28 h100
  text "FINISHED Cu" at 3858.62,6509.28 h100
  text "X-SECTION" at 5813.62,6509.28 h100
  text "X-SECTION" at 5813.62,6509.28 h100
  text "DIELECTRIC THICKNESS" at 7248.62,6492.62 h100
  text "DIELECTRIC THICKNESS" at 7248.62,6492.62 h100
  text "[INCHES]" at 8228.62,6267.62 h100
  text "[INCHES]" at 8228.62,6267.62 h100
  text "PRIMARY SIDE SILKSCREEN" at 1521.12,6209.28 h100
  text "PRIMARY SIDE SILKSCREEN" at 1521.12,6209.28 h100
  text "PRIMARY SIDE SOLDERMASK" at 1521.12,6034.28 h100
  text "PRIMARY SIDE SOLDERMASK" at 1521.12,6034.28 h100
  text "PRIMARY SIDE" at 2089.7,5867.21 h100
  text "L01" at 1121.12,5859.28 h100
  text "L01" at 1121.12,5859.28 h100
  text "1oz." at 4140.67,5859.28 h100
  text "0.0037" at 8348.62,5782.62 h100
  text "L02" at 1121.12,5684.28 h100
  text "L02" at 1121.12,5684.28 h100
  text "1oz." at 4138.62,5684.28 h100
  text "GROUND-PLANE-1" at 2040.61,5681.75 h100
  text "0.0050" at 8348.62,5607.62 h100
  text "L03" at 1121.12,5509.28 h100
  text "L03" at 1121.12,5509.28 h100
  text "1oz." at 4138.62,5509.28 h100
  text "INNER-SIGNAL-1" at 2101.11,5503.83 h100
  text "0.0120" at 8348.62,5432.62 h100
  text "GROUND-PLANE-2" at 2040.61,5349.01 h100
  text "L04" at 1121.12,5334.28 h100
  text "L04" at 1121.12,5334.28 h100
  text "1oz." at 4138.62,5334.28 h100
  text "1oz." at 4138.62,5334.28 h100
  text "0.0060" at 8348.62,5257.62 h100
  text "L05" at 1121.12,5159.28 h100
  text "L05" at 1121.12,5159.28 h100
  text "1oz." at 4138.62,5159.28 h100
  text "POWER-PLANE" at 2101.11,5153.83 h100
  text "0.0120" at 8348.62,5082.62 h100
  text "L06" at 1121.12,4984.28 h100
  text "L06" at 1121.12,4984.28 h100
  text "1oz." at 4138.62,4984.28 h100
  text "INNER-SIGNAL-2" at 2101.11,4978.83 h100
  text "0.0050" at 8348.62,4907.62 h100
  text "L07" at 1121.12,4809.28 h100
  text "L07" at 1121.12,4809.28 h100
  text "1oz." at 4138.62,4809.28 h100
  text "GROUND-PLANE-3" at 2101.11,4803.83 h100
  text "0.0037" at 8348.62,4732.62 h100
  text "L08" at 1121.12,4634.28 h100
  text "L08" at 1121.12,4634.28 h100
  text "1oz." at 4140.67,4634.28 h100
  text "SECONDARY SIDE" at 2101.11,4628.83 h100
  text "SECONDARY SIDE SOLDERMASK" at 1495.13,4465.33 h100
  text "SECONDARY SIDE SILKSCREEN" at 1506.04,4285.32 h100
  text "****IMPEDANCE REQUIREMENTS SHALL BE FOLLOWED :" at 783.32,4092.61 h100
  text "50 OHMS FOR 4.9210MIL, 100 OHMS DIFFERENTIAL FOR 3.976/8.268MIL" at 780.51,3901.59 h100
  text "& 90 OHMS DIFFERENTIAL FOR 5.118/8.268MIL" at 794.19,3682.74 h100
  text "PANEL FIDUCIALS SHALL BE ADDED DURING PANELIZATION" at 794.05,3437.77 h100
  text ".Layer_Name" at 25.82,-1252.19 h60
M13 Component Bodies Top:
  text ".Layer_Name" at 25.82,-1252.19 h60
M14 Component Bodies Bottom:
  text ".Layer_Name" at 25.82,-1252.19 h60
M15 Courtyards Top:
  text ".Layer_Name" at 25.82,-1252.19 h60
M16 Courtyards Bottom:
  text ".Layer_Name" at 25.82,-1252.19 h60
Drill Drawing:
  circle w10: c4621.66,-248.79 r27.63
  circle w10: c4621.66,497.13 r27.63
  circle w10: c4621.66,497.13 r16.58
  lines w10: 4594.04,-152.1 4594.04,-96.85 4649.29,-96.85 4649.29,-152.1 4594.04,-152.1 ; 4594.04,-0.15 4621.66,27.47 4649.29,-0.15 4621.66,-27.78 4594.04,-0.15 ; 4594.04,96.54 4607.85,96.54 4621.66,110.35 4635.48,96.54 4649.29,96.54 4649.29,110.35 4635.48,124.17 4649.29,137.98 4649.29,151.79 4635.48,151.79 4621.66,137.98 4607.85,151.79 4594.04,151.79 4594.04,137.98 4607.85,124.17 4594.04,110.35 4594.04,96.54 ; 4594.04,220.86 4607.85,248.49 4594.04,276.11 4621.66,262.3 4649.29,276.11 4635.48,248.49 4649.29,220.86 4621.66,234.67 4594.04,220.86 ; 4594.04,345.18 4594.04,400.43 4649.29,400.43 4649.29,345.18 4594.04,345.18 ; 4594.04,607.63 4594.04,635.26 4607.85,635.26 4607.85,649.07 4635.48,649.07 4635.48,635.26 4649.29,635.26 4649.29,607.63 4635.48,607.63 4635.48,593.82 4607.85,593.82 4607.85,607.63 4594.04,607.63 ; 4594.04,731.95 4607.85,745.77 4594.04,759.58 4607.85,759.58 4621.66,773.39 4635.48,759.58 4649.29,759.58 4635.48,745.77 4649.29,731.95 4635.48,731.95 4621.66,718.14 4607.85,731.95 4594.04,731.95 ; 4605.09,-141.05 4605.09,-107.9 4638.24,-107.9 4638.24,-141.05 4605.09,-141.05
  lines w12: 4543.95,-313.72 8166.48,-313.72 ; 4543.95,805.16 8166.48,805.16 ; 4881.81,-438.04 4881.81,929.48 ; 5213.81,-438.04 5213.81,929.48 ; 5850.37,-438.04 5850.37,929.48 ; 6109.51,-438.04 6109.51,929.48 ; 6484.67,-438.04 6484.67,929.48 ; 7754.29,-438.04 7754.29,929.48 ; 4543.95,-438.04 4543.95,929.48 8166.48,929.48 8166.48,-438.04 4543.95,-438.04
  text "Symbol" at 4618.54,842.46 h72
  text "Quantity" at 4919.11,842.46 h72
  text "Finished Hole Size" at 5251.11,842.46 h72
  text "Plated" at 5887.67,842.46 h72
  text "Hole Type" at 6146.81,842.46 h72
  text "Drill Layer Pair" at 6521.97,842.46 h72
  text "Tolerance" at 7791.59,842.46 h72
  text "2" at 4919.11,718.14 h60
  text "3,200mm (125,98mil)" at 5251.11,718.14 h60
  text "NPTH" at 5887.67,718.14 h60
  text "Round" at 6146.81,718.14 h60
  text "TopLayer - S1 (.GTL) - BottomLayer - S8 (.GBL)" at 6521.97,718.14 h60
  text "873" at 4919.11,593.82 h60
  text "0,200mm (7,87mil)" at 5251.11,593.82 h60
  text "PTH" at 5887.67,593.82 h60
  text "Round" at 6146.81,593.82 h60
  text "TopLayer - S1 (.GTL) - BottomLayer - S8 (.GBL)" at 6521.97,593.82 h60
  text "16" at 4919.11,469.5 h60
  text "0,890mm (35,04mil)" at 5251.11,469.5 h60
  text "PTH" at 5887.67,469.5 h60
  text "Round" at 6146.81,469.5 h60
  text "TopLayer - S1 (.GTL) - BottomLayer - S8 (.GBL)" at 6521.97,469.5 h60
  text "11" at 4919.11,345.18 h60
  text "1,016mm (40,00mil)" at 5251.11,345.18 h60
  text "PTH" at 5887.67,345.18 h60
  text "Round" at 6146.81,345.18 h60
  text "TopLayer - S1 (.GTL) - BottomLayer - S8 (.GBL)" at 6521.97,345.18 h60
  text "40" at 4919.11,220.86 h60
  text "1,150mm (45,28mil)" at 5251.11,220.86 h60
  text "PTH" at 5887.67,220.86 h60
  text "Round" at 6146.81,220.86 h60
  text "TopLayer - S1 (.GTL) - BottomLayer - S8 (.GBL)" at 6521.97,220.86 h60
  text "4" at 4919.11,96.54 h60
  text "1,570mm (61,81mil)" at 5251.11,96.54 h60
  text "PTH" at 5887.67,96.54 h60
  text "Round" at 6146.81,96.54 h60
  text "TopLayer - S1 (.GTL) - BottomLayer - S8 (.GBL)" at 6521.97,96.54 h60
  text "4" at 4919.11,-27.78 h60
  text "3,251mm (128,00mil)" at 5251.11,-27.78 h60
  text "PTH" at 5887.67,-27.78 h60
  text "Round" at 6146.81,-27.78 h60
  text "TopLayer - S1 (.GTL) - BottomLayer - S8 (.GBL)" at 6521.97,-27.78 h60
  text "2" at 4919.11,-152.1 h60
  text "0,760mm (29,92mil)" at 5251.11,-152.1 h60
  text "PTH" at 5887.67,-152.1 h60
  text "Slot" at 6146.81,-152.1 h60
  text "TopLayer - S1 (.GTL) - BottomLayer - S8 (.GBL)" at 6521.97,-152.1 h60
  text "1" at 4919.11,-276.42 h60
  text "1,010mm (39,76mil)" at 5251.11,-276.42 h60
  text "PTH" at 5887.67,-276.42 h60
  text "Slot" at 6146.81,-276.42 h60
  text "TopLayer - S1 (.GTL) - BottomLayer - S8 (.GBL)" at 6521.97,-276.42 h60
  text "953 Total" at 4919.11,-400.74 h60
  text "Slot definitions :" at 4618.54,-487.76 h60
  text "Routed Path Length" at 5069.26,-487.76 h60
  text "= Calculated from tool start centre position to tool end centre position." at 5608.99,-487.76 h60
  text "Hole Length" at 5069.26,-537.49 h60
  text "= Routed Path Length + Tool Size = Slot length as defined in the PCB layout" at 5409.19,-537.49 h60
  text ".Layer_Name" at 25.82,-1252.19 h60
M17 Embedded Cavity:
  text ".Layer_Name" at 25.82,-1252.19 h60
M18 Embedded Assembly:
  text ".Layer_Name" at 25.82,-1252.19 h60
M19 Embedded Keepout:
  text ".Layer_Name" at 25.82,-1252.19 h60

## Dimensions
0,2204.72 to 0,0 on M2 Board Dimensions
54.25,2411.57 to 0,2204.72 on M2 Board Dimensions
0,2204.72 to 1965.75,2002.36 on M2 Board Dimensions
0,2204.72 to 614.17,2137.8 on M2 Board Dimensions
0,2204.72 to 234.25,2106.57 on M2 Board Dimensions
236.22,-400 to 1236.22,-400 on M2 Board Dimensions
0,2204.72 to 3464.57,2204.72 on M2 Board Dimensions
3326.77,137.8 to 3464.57,0 on M2 Board Dimensions
3326.77,2066.93 to 3326.77,137.8 on M2 Board Dimensions
3464.57,2204.72 to 3326.77,2066.93 on M2 Board Dimensions
3326.77,2066.93 to 3464.57,2204.72 on M2 Board Dimensions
